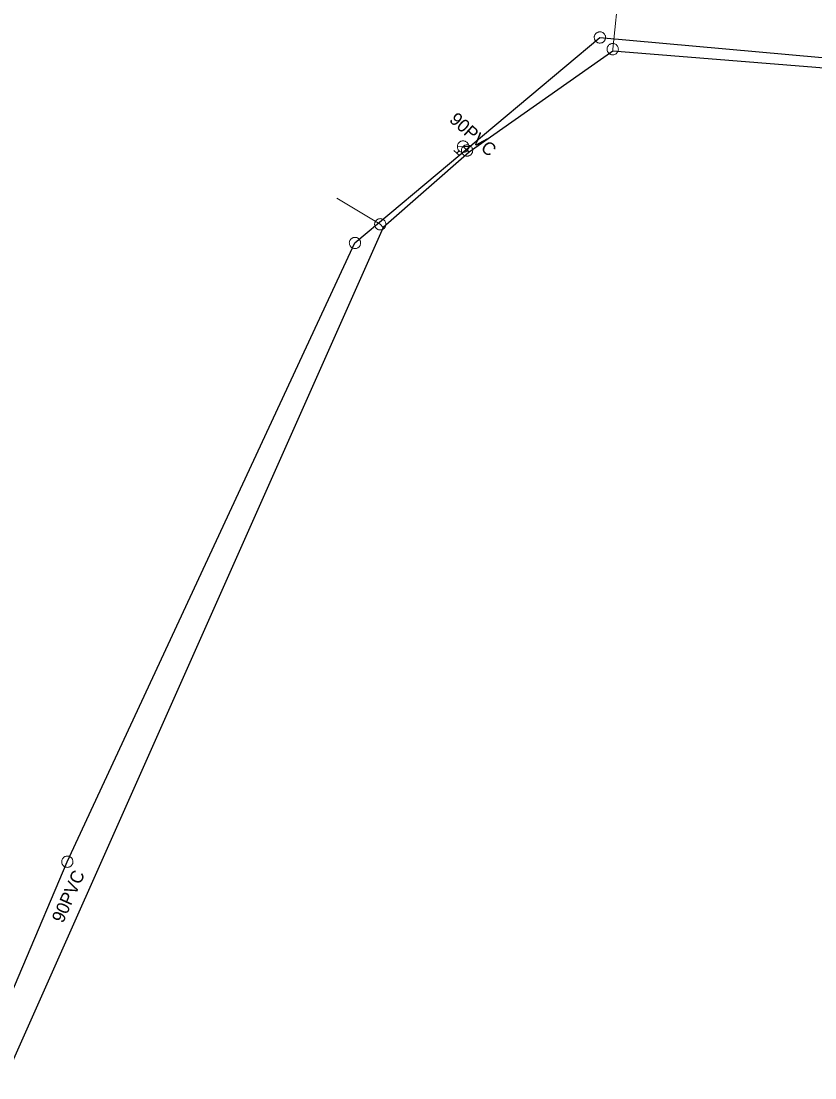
# Model space of a CAD drawing. Extents: x -741806 to -738704, y -1059275 to -1055387.
# Drawn here: x -740869.8 to -740808.2, y -1058132 to -1058050 of the extents above; entities that cross this region are included whole.
import ezdxf

# ---------------------------------------------------------------- set-up
doc = ezdxf.new("R2010")
doc.units = 0
doc.header["$LTSCALE"] = 0.4
for name, color, linetype, lineweight in [('2', 7, 'Continuous', 25), ('21', 7, 'Continuous', 13), ('3', 7, 'Continuous', 13), ('50', 7, 'Continuous', 13), ('51', 7, 'Continuous', 13), ('52', 7, 'Continuous', 25)]:
    doc.layers.add(name, color=color, linetype=linetype, lineweight=lineweight)
doc.layers.add('53', color=7, linetype='Continuous')

msp = doc.modelspace()

# ---------------------------------------------------------------- linework, layer by layer
at = {"layer": '2'}
for points in [[(-740907.18, -1058212.62), (-740886.85, -1058163.899), (-740866.18, -1058115.19), (-740843.879, -1058067.21), (-740824.89, -1058051.27)], [(-740824.89, -1058051.27), (-740778.35, -1058055.46), (-740728.07, -1058059.94), (-740708.829, -1058061.48), (-740678.949, -1058063.95), (-740625.71, -1058070.179)]]:
    msp.add_lwpolyline(points, dxfattribs=at)
at = {"layer": '21'}
for points in [[(-740823.883, -1058052.338), (-740823.899, -1058052.179), (-740823.397, -1058047.402)], [(-740841.695, -1058066.003), (-740841.92, -1058065.76), (-740845.285, -1058063.73)]]:
    msp.add_lwpolyline(points, dxfattribs=at)
at = {"layer": '3'}
for points in [[(-740824.554, -1058050.988), (-740824.585, -1058050.956), (-740824.619, -1058050.926), (-740824.657, -1058050.899), (-740824.697, -1058050.877), (-740824.739, -1058050.859), (-740824.783, -1058050.845), (-740824.828, -1058050.837), (-740824.874, -1058050.833), (-740824.919, -1058050.834), (-740824.964, -1058050.84), (-740825.009, -1058050.85), (-740825.053, -1058050.864), (-740825.094, -1058050.884), (-740825.134, -1058050.907), (-740825.17, -1058050.935), (-740825.204, -1058050.966), (-740825.233, -1058051.001), (-740825.26, -1058051.038), (-740825.282, -1058051.079), (-740825.3, -1058051.121), (-740825.313, -1058051.165), (-740825.322, -1058051.209), (-740825.326, -1058051.255), (-740825.326, -1058051.301), (-740825.32, -1058051.347), (-740825.309, -1058051.391), (-740825.295, -1058051.434), (-740825.275, -1058051.476), (-740825.251, -1058051.515), (-740825.223, -1058051.552), (-740825.193, -1058051.585), (-740825.158, -1058051.615), (-740825.12, -1058051.642), (-740825.08, -1058051.664), (-740825.039, -1058051.681), (-740824.994, -1058051.695), (-740824.95, -1058051.703), (-740824.903, -1058051.707), (-740824.858, -1058051.706), (-740824.813, -1058051.701), (-740824.768, -1058051.691), (-740824.724, -1058051.676), (-740824.683, -1058051.657), (-740824.644, -1058051.633), (-740824.608, -1058051.605), (-740824.574, -1058051.574), (-740824.544, -1058051.54), (-740824.518, -1058051.502), (-740824.496, -1058051.462), (-740824.478, -1058051.419), (-740824.465, -1058051.376), (-740824.455, -1058051.331), (-740824.452, -1058051.285), (-740824.452, -1058051.24), (-740824.458, -1058051.194), (-740824.468, -1058051.149), (-740824.483, -1058051.107), (-740824.503, -1058051.064), (-740824.526, -1058051.025), (-740824.553, -1058050.989)], [(-740866.008, -1058114.786), (-740866.051, -1058114.772), (-740866.095, -1058114.761), (-740866.141, -1058114.754), (-740866.186, -1058114.752), (-740866.232, -1058114.756), (-740866.277, -1058114.763), (-740866.321, -1058114.776), (-740866.364, -1058114.793), (-740866.404, -1058114.815), (-740866.441, -1058114.84), (-740866.477, -1058114.87), (-740866.509, -1058114.903), (-740866.537, -1058114.939), (-740866.562, -1058114.977), (-740866.581, -1058115.019), (-740866.597, -1058115.062), (-740866.608, -1058115.107), (-740866.615, -1058115.151), (-740866.616, -1058115.198), (-740866.613, -1058115.244), (-740866.604, -1058115.288), (-740866.592, -1058115.332), (-740866.575, -1058115.375), (-740866.554, -1058115.415), (-740866.528, -1058115.453), (-740866.498, -1058115.488), (-740866.466, -1058115.52), (-740866.429, -1058115.549), (-740866.39, -1058115.573), (-740866.349, -1058115.592), (-740866.307, -1058115.608), (-740866.262, -1058115.619), (-740866.216, -1058115.626), (-740866.17, -1058115.627), (-740866.125, -1058115.624), (-740866.08, -1058115.616), (-740866.036, -1058115.603), (-740865.993, -1058115.586), (-740865.954, -1058115.565), (-740865.916, -1058115.539), (-740865.88, -1058115.51), (-740865.848, -1058115.477), (-740865.82, -1058115.441), (-740865.796, -1058115.402), (-740865.776, -1058115.361), (-740865.76, -1058115.318), (-740865.749, -1058115.274), (-740865.742, -1058115.228), (-740865.741, -1058115.182), (-740865.745, -1058115.136), (-740865.753, -1058115.091), (-740865.764, -1058115.047), (-740865.782, -1058115.005), (-740865.803, -1058114.965), (-740865.829, -1058114.926), (-740865.859, -1058114.891), (-740865.891, -1058114.86), (-740865.928, -1058114.831), (-740865.967, -1058114.807), (-740866.007, -1058114.787)]]:
    msp.add_lwpolyline(points, dxfattribs=at)
msp.add_lwpolyline([(-740843.693, -1058066.813), (-740843.736, -1058066.796), (-740843.779, -1058066.784), (-740843.825, -1058066.776), (-740843.87, -1058066.772), (-740843.916, -1058066.774), (-740843.962, -1058066.78), (-740844.006, -1058066.792), (-740844.049, -1058066.807), (-740844.09, -1058066.828), (-740844.129, -1058066.852), (-740844.165, -1058066.88), (-740844.198, -1058066.912), (-740844.227, -1058066.947), (-740844.253, -1058066.985), (-740844.274, -1058067.026), (-740844.292, -1058067.068), (-740844.304, -1058067.112), (-740844.312, -1058067.157), (-740844.315, -1058067.203), (-740844.313, -1058067.249), (-740844.306, -1058067.294), (-740844.296, -1058067.338), (-740844.28, -1058067.381), (-740844.26, -1058067.422), (-740844.235, -1058067.462), (-740844.207, -1058067.497), (-740844.176, -1058067.53), (-740844.14, -1058067.56), (-740844.102, -1058067.585), (-740844.061, -1058067.606), (-740844.02, -1058067.624), (-740843.976, -1058067.636), (-740843.93, -1058067.644), (-740843.884, -1058067.647), (-740843.839, -1058067.646), (-740843.793, -1058067.639), (-740843.749, -1058067.628), (-740843.705, -1058067.612), (-740843.665, -1058067.592), (-740843.627, -1058067.568), (-740843.59, -1058067.54), (-740843.557, -1058067.508), (-740843.527, -1058067.473), (-740843.502, -1058067.435), (-740843.481, -1058067.394), (-740843.463, -1058067.352), (-740843.451, -1058067.308), (-740843.443, -1058067.263), (-740843.44, -1058067.217), (-740843.442, -1058067.171), (-740843.449, -1058067.126), (-740843.459, -1058067.081), (-740843.475, -1058067.038), (-740843.495, -1058066.997), (-740843.52, -1058066.958), (-740843.548, -1058066.922), (-740843.579, -1058066.89), (-740843.615, -1058066.86), (-740843.653, -1058066.835)], close=True, dxfattribs=at)
at = {"layer": '50'}
for p, q in [((-740836.202, -1058060.025), (-740835.981, -1058060.239)), ((-740835.807, -1058060.058), (-740835.981, -1058060.239)), ((-740835.76, -1058060.453), (-740835.981, -1058060.239)), ((-740835.496, -1058059.736), (-740835.94, -1058059.741)), ((-740835.496, -1058059.736), (-740835.048, -1058059.729))]:
    msp.add_line(p, q, dxfattribs=at)
msp.add_lwpolyline([(-740835.813, -1058059.425), (-740835.845, -1058059.462), (-740835.873, -1058059.498), (-740835.896, -1058059.541), (-740835.913, -1058059.583), (-740835.927, -1058059.625), (-740835.937, -1058059.673), (-740835.94, -1058059.719), (-740835.941, -1058059.767), (-740835.936, -1058059.813), (-740835.924, -1058059.858), (-740835.91, -1058059.902), (-740835.893, -1058059.946), (-740835.866, -1058059.985), (-740835.839, -1058060.023), (-740835.808, -1058060.057), (-740835.773, -1058060.087), (-740835.737, -1058060.114), (-740835.695, -1058060.137), (-740835.651, -1058060.155), (-740835.606, -1058060.17), (-740835.561, -1058060.179), (-740835.514, -1058060.184), (-740835.468, -1058060.183), (-740835.423, -1058060.178), (-740835.375, -1058060.168), (-740835.331, -1058060.154), (-740835.29, -1058060.134), (-740835.248, -1058060.111), (-740835.212, -1058060.081), (-740835.176, -1058060.052), (-740835.145, -1058060.016), (-740835.118, -1058059.977), (-740835.096, -1058059.938), (-740835.076, -1058059.894), (-740835.063, -1058059.849), (-740835.053, -1058059.804), (-740835.05, -1058059.758), (-740835.048, -1058059.711), (-740835.055, -1058059.663), (-740835.065, -1058059.619), (-740835.081, -1058059.573), (-740835.101, -1058059.532), (-740835.122, -1058059.492), (-740835.152, -1058059.452), (-740835.183, -1058059.418), (-740835.218, -1058059.388), (-740835.256, -1058059.362), (-740835.297, -1058059.338), (-740835.339, -1058059.319), (-740835.385, -1058059.305), (-740835.429, -1058059.296), (-740835.478, -1058059.291), (-740835.523, -1058059.292), (-740835.569, -1058059.296), (-740835.614, -1058059.309), (-740835.659, -1058059.321), (-740835.702, -1058059.341), (-740835.741, -1058059.366), (-740835.779, -1058059.394)], close=True, dxfattribs=at)
at = {"layer": '51'}
for points in [[(-740823.945, -1058051.744), (-740823.989, -1058051.751), (-740824.033, -1058051.763), (-740824.077, -1058051.779), (-740824.117, -1058051.8), (-740824.155, -1058051.825), (-740824.191, -1058051.854), (-740824.223, -1058051.887), (-740824.252, -1058051.922), (-740824.276, -1058051.961), (-740824.297, -1058052.001), (-740824.314, -1058052.044), (-740824.326, -1058052.089), (-740824.333, -1058052.134), (-740824.335, -1058052.179), (-740824.332, -1058052.225), (-740824.326, -1058052.271), (-740824.314, -1058052.315), (-740824.297, -1058052.357), (-740824.276, -1058052.398), (-740824.25, -1058052.437), (-740824.221, -1058052.472), (-740824.19, -1058052.505), (-740824.154, -1058052.533), (-740824.116, -1058052.558), (-740824.074, -1058052.579), (-740824.031, -1058052.595), (-740823.988, -1058052.607), (-740823.942, -1058052.614), (-740823.896, -1058052.616), (-740823.85, -1058052.614), (-740823.806, -1058052.606), (-740823.762, -1058052.594), (-740823.718, -1058052.578), (-740823.678, -1058052.557), (-740823.64, -1058052.532), (-740823.604, -1058052.503), (-740823.572, -1058052.47), (-740823.543, -1058052.435), (-740823.519, -1058052.396), (-740823.498, -1058052.356), (-740823.481, -1058052.313), (-740823.469, -1058052.268), (-740823.463, -1058052.223), (-740823.46, -1058052.178), (-740823.463, -1058052.132), (-740823.469, -1058052.086), (-740823.482, -1058052.042), (-740823.498, -1058052), (-740823.519, -1058051.959), (-740823.545, -1058051.92), (-740823.574, -1058051.885), (-740823.605, -1058051.852), (-740823.641, -1058051.824), (-740823.679, -1058051.799), (-740823.721, -1058051.778), (-740823.764, -1058051.762), (-740823.807, -1058051.75), (-740823.853, -1058051.743), (-740823.899, -1058051.741), (-740823.944, -1058051.744)], [(-740835.537, -1058059.774), (-740835.562, -1058059.811), (-740835.584, -1058059.851), (-740835.602, -1058059.894), (-740835.615, -1058059.937), (-740835.623, -1058059.982), (-740835.627, -1058060.029), (-740835.625, -1058060.074), (-740835.619, -1058060.12), (-740835.608, -1058060.164), (-740835.593, -1058060.207), (-740835.573, -1058060.248), (-740835.549, -1058060.288), (-740835.521, -1058060.324), (-740835.49, -1058060.357), (-740835.454, -1058060.386), (-740835.417, -1058060.413), (-740835.377, -1058060.434), (-740835.334, -1058060.452), (-740835.29, -1058060.464), (-740835.245, -1058060.472), (-740835.199, -1058060.476), (-740835.154, -1058060.475), (-740835.108, -1058060.468), (-740835.064, -1058060.458), (-740835.02, -1058060.442), (-740834.979, -1058060.423), (-740834.941, -1058060.399), (-740834.904, -1058060.37), (-740834.871, -1058060.339), (-740834.84, -1058060.304), (-740834.816, -1058060.267), (-740834.794, -1058060.227), (-740834.776, -1058060.183), (-740834.763, -1058060.14), (-740834.755, -1058060.095), (-740834.751, -1058060.049), (-740834.753, -1058060.003), (-740834.758, -1058059.958), (-740834.77, -1058059.914), (-740834.785, -1058059.871), (-740834.805, -1058059.829), (-740834.829, -1058059.79), (-740834.857, -1058059.754), (-740834.888, -1058059.721), (-740834.923, -1058059.691), (-740834.961, -1058059.665), (-740835.002, -1058059.644), (-740835.043, -1058059.626), (-740835.088, -1058059.613), (-740835.133, -1058059.605), (-740835.179, -1058059.602), (-740835.224, -1058059.602), (-740835.27, -1058059.609), (-740835.314, -1058059.619), (-740835.357, -1058059.635), (-740835.399, -1058059.655), (-740835.437, -1058059.679), (-740835.474, -1058059.707), (-740835.507, -1058059.739), (-740835.536, -1058059.773)], [(-740841.483, -1058065.76), (-740841.485, -1058065.715), (-740841.492, -1058065.67), (-740841.504, -1058065.625), (-740841.52, -1058065.583), (-740841.541, -1058065.542), (-740841.566, -1058065.503), (-740841.595, -1058065.468), (-740841.627, -1058065.435), (-740841.663, -1058065.407), (-740841.701, -1058065.382), (-740841.742, -1058065.361), (-740841.785, -1058065.344), (-740841.829, -1058065.332), (-740841.874, -1058065.325), (-740841.92, -1058065.323), (-740841.966, -1058065.325), (-740842.011, -1058065.332), (-740842.055, -1058065.344), (-740842.098, -1058065.361), (-740842.139, -1058065.382), (-740842.177, -1058065.407), (-740842.213, -1058065.435), (-740842.245, -1058065.468), (-740842.274, -1058065.503), (-740842.299, -1058065.542), (-740842.32, -1058065.583), (-740842.336, -1058065.625), (-740842.348, -1058065.67), (-740842.355, -1058065.715), (-740842.358, -1058065.761), (-740842.355, -1058065.806), (-740842.348, -1058065.851), (-740842.336, -1058065.896), (-740842.32, -1058065.938), (-740842.299, -1058065.979), (-740842.274, -1058066.018), (-740842.245, -1058066.053), (-740842.213, -1058066.086), (-740842.177, -1058066.114), (-740842.139, -1058066.139), (-740842.098, -1058066.16), (-740842.055, -1058066.177), (-740842.011, -1058066.188), (-740841.966, -1058066.196), (-740841.92, -1058066.198), (-740841.874, -1058066.196), (-740841.829, -1058066.188), (-740841.785, -1058066.177), (-740841.742, -1058066.16), (-740841.701, -1058066.139), (-740841.663, -1058066.114), (-740841.627, -1058066.086), (-740841.595, -1058066.053), (-740841.566, -1058066.018), (-740841.541, -1058065.979), (-740841.52, -1058065.938), (-740841.504, -1058065.896), (-740841.492, -1058065.851), (-740841.485, -1058065.806), (-740841.483, -1058065.761)]]:
    msp.add_lwpolyline(points, dxfattribs=at)
at = {"layer": '52'}
for points in [[(-740626.537, -1058069.271), (-740626.965, -1058069.033), (-740656.548, -1058067.382), (-740672.59, -1058065.485), (-740708.822, -1058062.591), (-740710.671, -1058062.095), (-740751.42, -1058058.46), (-740773.993, -1058056.467), (-740779.522, -1058055.831), (-740794.666, -1058054.688), (-740823.883, -1058052.338), (-740835.024, -1058060.166), (-740841.695, -1058066.003), (-740887.96, -1058170.041), (-740903.829, -1058207.8), (-740906.75, -1058213.899)], [(-740835.024, -1058060.166), (-740835.19, -1058060.04), (-740835.5, -1058059.74)]]:
    msp.add_lwpolyline(points, dxfattribs=at)

# ---------------------------------------------------------------- texts
at = {"layer": '53'}
for rotation, p in [(318, (-740836.631, -1058057.736)), (66, (-740866.514, -1058120.007))]:
    msp.add_text('90PVC ', height=1, rotation=rotation, dxfattribs=at).set_placement(p)

doc.saveas('drawing.dxf')
